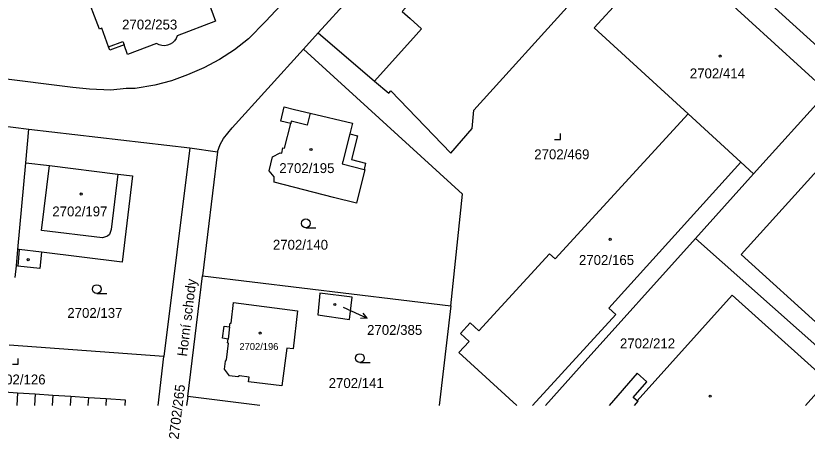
# Model space of a CAD drawing. Extents: x -496682 to -495776, y -1088797 to -1088018.
# Drawn here: x -496329.9 to -496193.9, y -1088575.2 to -1088502.5 of the extents above; entities that cross this region are included whole.
import ezdxf

# ---------------------------------------------------------------- set-up
doc = ezdxf.new("R2010")
doc.units = 0
for name, color, linetype in [('Hranice parcel', 7, 'Continuous'), ('Parcelní čísla', 7, 'Continuous'), ('Pop  PČ popisy', 7, 'Continuous'), ('Vnitřní kresba', 7, 'Continuous'), ('Značky budov', 7, 'Continuous'), ('Značky kultur', 7, 'Continuous')]:
    doc.layers.add(name, color=color, linetype=linetype)

msp = doc.modelspace()

# ---------------------------------------------------------------- linework, layer by layer
at = {"layer": 'Hranice parcel'}
for p, q in [((-496277.9, -1088505.38), (-496249.99, -1088474.77)), ((-496280.44, -1088508.2), (-496277.9, -1088505.38)), ((-496277.9, -1088505.38), (-496268.24, -1088513.68)), ((-496203.08, -1088529.64), (-496190.39, -1088515.55)), ((-496205.29, -1088527.62), (-496214.35, -1088519.32)), ((-496341.52, -1088520.23), (-496327.65, -1088521.96)), ((-496328.17, -1088527.72), (-496327.65, -1088521.96)), ((-496327.65, -1088521.96), (-496300.01, -1088525.15)), ((-496300.01, -1088525.15), (-496304.43, -1088561.01)), ((-496300.01, -1088525.15), (-496295.23, -1088525.87)), ((-496295.23, -1088525.87), (-496297.81, -1088547.13)), ((-496205.29, -1088527.62), (-496203.08, -1088529.64)), ((-496213.05, -1088540.72), (-496203.08, -1088529.64)), ((-496180.77, -1088569.45), (-496213.05, -1088540.72)), ((-496330.02, -1088547.42), (-496329.78, -1088545.45)), ((-496300.36, -1088567.89), (-496297.81, -1088547.13)), ((-496297.81, -1088547.13), (-496255.13, -1088552.31)), ((-496255.13, -1088552.31), (-496257.1, -1088569.45)), ((-496304.43, -1088561.01), (-496331.02, -1088559.09)), ((-496305.44, -1088569.45), (-496304.43, -1088561.01)), ((-496332.64, -1088567.05), (-496329.59, -1088567.25)), ((-496329.59, -1088567.25), (-496329.73, -1088569.45)), ((-496329.59, -1088567.25), (-496326.55, -1088567.45)), ((-496326.55, -1088567.45), (-496326.68, -1088569.45)), ((-496326.55, -1088567.45), (-496323.51, -1088567.65)), ((-496323.51, -1088567.65), (-496323.63, -1088569.45)), ((-496323.51, -1088567.65), (-496320.46, -1088567.85)), ((-496320.46, -1088567.85), (-496320.57, -1088569.45)), ((-496320.46, -1088567.85), (-496317.42, -1088568.05)), ((-496317.42, -1088568.05), (-496317.51, -1088569.45)), ((-496317.42, -1088568.05), (-496314.37, -1088568.25)), ((-496314.37, -1088568.25), (-496314.45, -1088569.45)), ((-496300.36, -1088567.89), (-496300.54, -1088569.45))]:
    msp.add_line(p, q, dxfattribs=at)
for points in [[(-496244.2, -1088466.33), (-496242.71, -1088465.41), (-496240.93, -1088464.91), (-496239.45, -1088465.16), (-496238.15, -1088465.99), (-496132.08, -1088562.07), (-496131.43, -1088562.99), (-496131.42, -1088564), (-496132.07, -1088565.26)], [(-496245.99, -1088478.39), (-496247.4, -1088479.95), (-496245.31, -1088481.83), (-496263.51, -1088501.71), (-496262.11, -1088502.91), (-496260.17, -1088504.72), (-496261.08, -1088505.74), (-496268.24, -1088513.68)], [(-496305.69, -1088507.24), (-496310.68, -1088509.11), (-496311.29, -1088507.46), (-496313.75, -1088508.38), (-496313.97, -1088507.79), (-496315.1, -1088504.6), (-496315.52, -1088504.76), (-496317.97, -1088498.28), (-496310.64, -1088495.51), (-496309.98, -1088497.27), (-496305.9, -1088495.73), (-496307.18, -1088492.33), (-496300.54, -1088489.82), (-496295.6, -1088503.41), (-496302.16, -1088505.89)], [(-496190.39, -1088515.55), (-496208.5, -1088499), (-496217.64, -1088490.55)], [(-496268.24, -1088513.68), (-496265.8, -1088515.77), (-496265.43, -1088515.37), (-496255.1, -1088526.07), (-496251.45, -1088521.81), (-496251.15, -1088518.66), (-496234.05, -1088499.76), (-496231.37, -1088491.6)], [(-496221.19, -1088494.41), (-496230.49, -1088504.55), (-496214.35, -1088519.32)], [(-496282.64, -1088498.73), (-496287, -1088503.42), (-496289.92, -1088506.42), (-496292.31, -1088508.31), (-496294.86, -1088509.98), (-496297.59, -1088511.42), (-496300.41, -1088512.61), (-496303.13, -1088513.62), (-496305.98, -1088514.4), (-496309.41, -1088514.94), (-496310.93, -1088514.97), (-496313.55, -1088515.26), (-496317.24, -1088515.06), (-496320.12, -1088514.76), (-496333.4, -1088513.15)], [(-496302.16, -1088505.89), (-496302.34, -1088506.34), (-496302.61, -1088506.75), (-496302.95, -1088507.09), (-496303.36, -1088507.35), (-496303.82, -1088507.53), (-496304.3, -1088507.6), (-496304.79, -1088507.58), (-496305.26, -1088507.46), (-496305.69, -1088507.24)], [(-496295.23, -1088525.87), (-496294.76, -1088524.6), (-496294.18, -1088523.56), (-496292.73, -1088521.72), (-496280.44, -1088508.2)], [(-496255.13, -1088552.31), (-496253.14, -1088533.12), (-496280.44, -1088508.2)], [(-496272.18, -1088527.18), (-496269.77, -1088527.8), (-496270.02, -1088528.86), (-496269.9, -1088528.89), (-496271.35, -1088534.65), (-496275.27, -1088533.67), (-496285.51, -1088531.07), (-496285.49, -1088530.11), (-496286.36, -1088529.12), (-496285.77, -1088526.72), (-496284.46, -1088526.04), (-496284.2, -1088526.06), (-496283.99, -1088525.16), (-496283.7, -1088525.23), (-496282.65, -1088520.96), (-496284.33, -1088520.55), (-496283.8, -1088518.12), (-496281.99, -1088518.55), (-496279.33, -1088519.18), (-496272.01, -1088520.93), (-496272.51, -1088522.77), (-496271.14, -1088523.12), (-496272.18, -1088527.18)], [(-496214.35, -1088519.32), (-496237.18, -1088544.25), (-496238.15, -1088543.36), (-496250.3, -1088556.62), (-496251.8, -1088555.25), (-496253.46, -1088557.05), (-496251.95, -1088558.43), (-496253.72, -1088560.35), (-496243.79, -1088569.45)], [(-496170.45, -1088533.31), (-496191.17, -1088556.18), (-496205.21, -1088543.51), (-496184.56, -1088520.66)], [(-496329.78, -1088545.45), (-496329.53, -1088542.61), (-496328.17, -1088527.72)], [(-496328.17, -1088527.72), (-496324.13, -1088528.21), (-496312.38, -1088529.66)], [(-496241.07, -1088569.45), (-496226.75, -1088553.82), (-496227.98, -1088552.7), (-496205.29, -1088527.62)], [(-496312.38, -1088529.66), (-496309.87, -1088529.96), (-496311.62, -1088544.81), (-496325.46, -1088543.11)], [(-496213.05, -1088540.72), (-496233.07, -1088562.96), (-496238.87, -1088569.45)], [(-496325.46, -1088543.11), (-496325.75, -1088545.88), (-496329.53, -1088545.48), (-496329.78, -1088545.45)], [(-496272.06, -1088550.82), (-496277.62, -1088550.13), (-496278.01, -1088553.84), (-496272.54, -1088554.66), (-496272.06, -1088550.82)], [(-496194.13, -1088569.45), (-496190.36, -1088565.18), (-496206.75, -1088550.46), (-496223.07, -1088568.62), (-496223.75, -1088568.03), (-496221.41, -1088565.34), (-496223.08, -1088563.9), (-496227.89, -1088569.45)], [(-496291.47, -1088564.36), (-496291.75, -1088564.53), (-496293.19, -1088564.36), (-496294.05, -1088563.16), (-496293.88, -1088561.8), (-496293.68, -1088561.61), (-496293.33, -1088558.7), (-496293.49, -1088558.66), (-496293.41, -1088558.01), (-496294.37, -1088557.89), (-496294.09, -1088555.81), (-496293.15, -1088555.93), (-496293.06, -1088555.28), (-496292.91, -1088555.28), (-496292.48, -1088551.75), (-496281.49, -1088553.16), (-496282.22, -1088559.69), (-496283.33, -1088559.6), (-496284.17, -1088566.05), (-496289.9, -1088565.34)], [(-496289.9, -1088565.34), (-496289.8, -1088564.54), (-496291.47, -1088564.36)], [(-496314.37, -1088568.25), (-496311.08, -1088568.47), (-496311.14, -1088569.45)], [(-496287.95, -1088569.45), (-496300.36, -1088567.89)]]:
    msp.add_lwpolyline(points, dxfattribs=at)
at = {"layer": 'Pop  PČ popisy'}
for p, q in [((-496273.63, -1088552.52), (-496272.23, -1088553.18)), ((-496272.23, -1088553.18), (-496269.51, -1088554.45)), ((-496269.51, -1088554.45), (-496270.21, -1088553.57)), ((-496269.51, -1088554.45), (-496270.63, -1088554.48))]:
    msp.add_line(p, q, dxfattribs=at)
at = {"layer": 'Vnitřní kresba'}
for p, q in [((-496313.97, -1088507.79), (-496311.51, -1088506.88)), ((-496311.51, -1088506.88), (-496311.29, -1088507.46)), ((-496279.33, -1088519.18), (-496279.82, -1088521.27)), ((-496282.56, -1088520.59), (-496282.65, -1088520.96)), ((-496279.82, -1088521.27), (-496282.56, -1088520.59)), ((-496272.51, -1088522.77), (-496273.69, -1088527.5)), ((-496273.69, -1088527.5), (-496273.8, -1088527.93)), ((-496325.46, -1088539.38), (-496324.13, -1088528.21)), ((-496273.8, -1088527.93), (-496270.02, -1088528.86)), ((-496312.38, -1088529.66), (-496313.5, -1088539.2)), ((-496315.02, -1088540.61), (-496325.46, -1088539.38)), ((-496313.79, -1088540.07), (-496314.16, -1088540.32)), ((-496313.5, -1088539.2), (-496313.79, -1088540.07)), ((-496314.16, -1088540.32), (-496315.02, -1088540.61)), ((-496329.31, -1088542.64), (-496329.53, -1088542.61)), ((-496329.31, -1088542.64), (-496329.53, -1088545.48)), ((-496325.46, -1088543.11), (-496329.31, -1088542.64)), ((-496293.15, -1088555.93), (-496293.41, -1088558.01)), ((-496222.98, -1088568.7), (-496223.63, -1088569.45)), ((-496223.07, -1088568.62), (-496222.98, -1088568.7))]:
    msp.add_line(p, q, dxfattribs=at)
at = {"layer": 'Značky budov'}
for centre in [(-496208.84, -1088509.38), (-496279.16, -1088525.43), (-496318.66, -1088533.09), (-496227.72, -1088540.88), (-496327.79, -1088544.37), (-496275.05, -1088552.07), (-496287.88, -1088556.98), (-496210.55, -1088567.84)]:
    msp.add_circle(centre, 0.175, dxfattribs=at)
at = {"layer": 'Značky kultur'}
for p, q in [((-496237.29, -1088523.7), (-496236.29, -1088523.7)), ((-496236.29, -1088523.7), (-496236.29, -1088522.7)), ((-496280.06, -1088538.88), (-496278.31, -1088538.88)), ((-496315.99, -1088550.17), (-496314.24, -1088550.17)), ((-496329.49, -1088562.33), (-496329.49, -1088561.33)), ((-496330.49, -1088562.33), (-496329.49, -1088562.33)), ((-496270.75, -1088562.03), (-496269, -1088562.03))]:
    msp.add_line(p, q, dxfattribs=at)
for centre in [(-496280.06, -1088538.13), (-496315.99, -1088549.42), (-496270.75, -1088561.28)]:
    msp.add_circle(centre, 0.75, dxfattribs=at)

# ---------------------------------------------------------------- texts
at = {"layer": 'Parcelní čísla'}
for s, height, p in [('2702/253', 1.7, (-496311.63, -1088504.82)), ('2702/414', 1.7, (-496214.04, -1088513.21)), ('2702/469', 1.7, (-496240.78, -1088527.12)), ('2702/195', 1.7, (-496284.61, -1088529.49)), ('2702/197', 1.7, (-496323.63, -1088536.93)), ('2702/140', 1.7, (-496285.71, -1088542.66)), ('2702/165', 1.7, (-496233.1, -1088545.28)), ('2702/137', 1.7, (-496321.05, -1088554.37)), ('2702/385', 1.7, (-496269.52, -1088557.3)), ('2702/212', 1.7, (-496226.05, -1088559.61)), ('2702/196', 1.2, (-496291.46, -1088559.9)), ('2702/126', 1.7, (-496334.27, -1088565.81)), ('2702/141', 1.7, (-496276.12, -1088566.43))]:
    msp.add_text(s, height=height, dxfattribs=at).set_placement(p)
msp.add_text('2702/265', height=1.7, rotation=83, dxfattribs=at).set_placement((-496301.94, -1088575.33))
at = {"layer": 'Pop  PČ popisy'}
msp.add_text('Horní schody', height=1.7, rotation=83, dxfattribs=at).set_placement((-496300.48, -1088561.08))

doc.saveas('drawing.dxf')
